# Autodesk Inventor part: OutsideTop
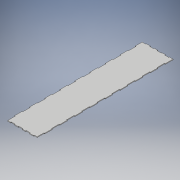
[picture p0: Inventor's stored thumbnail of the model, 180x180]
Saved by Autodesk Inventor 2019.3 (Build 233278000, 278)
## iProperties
Created: 2020-02
Part Number: OutsideTop
Material: Generic
Document SubType Name: Modeling
Designer: KrystynWikoff
Density: 1 g/cm^3
Appearance: Default
Author: KrystynWikoff
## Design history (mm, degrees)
sketch "Sketch1"
  geometry: L1 (0, 0)-(101.6, 0); L2 (101.6, 0)-(101.6, -457.2); L3 (101.6, -457.2)-(0, -457.2); L4 (0, -457.2)-(0, 0)
  constraints: 8 end point, 2 parallel, 1 horizontal, 1 perpendicular
  dimensions: "d0" = 457.2 distance of L3.end L1.start; "d1" = 101.6 distance of L1.start L1.end
extrude "Extrusion1" new body sketch "Sketch1" distance "d2" = 2.3622; taper "d3" = 0 deg
sketch "Sketch2" dims "d11" = 25.4
  geometry: L1 (-101.6, 0)-(0, 0) reference; L2 (0, 0)-(-2.362, 0); L3 (-2.362, 0)-(-2.362, 25.4); L4 (-2.362, 25.4)-(0, 25.4); L5 (0, 25.4)-(0, 0); L6 (0, 50.8)-(-2.362, 50.8); L7 (-2.362, 50.8)-(-2.362, 76.2); L8 (-2.362, 76.2)-(0, 76.2); L9 (0, 76.2)-(0, 50.8); L10 (0, 101.6)-(-2.362, 101.6); L11 (-2.362, 101.6)-(-2.362, 127); L12 (-2.362, 127)-(0, 127); L13 (0, 127)-(0, 101.6); L14 (0, 152.4)-(-2.362, 152.4); L15 (-2.362, 152.4)-(-2.362, 177.8); L16 (-2.362, 177.8)-(0, 177.8); L17 (0, 177.8)-(0, 152.4); L18 (0, 203.2)-(-2.362, 203.2); L19 (-2.362, 203.2)-(-2.362, 228.6); L20 (-2.362, 228.6)-(0, 228.6); L21 (0, 228.6)-(0, 203.2); L22 (0, 254)-(-2.362, 254); L23 (-2.362, 254)-(-2.362, 279.4); L24 (-2.362, 279.4)-(0, 279.4); L25 (0, 279.4)-(0, 254); L26 (0, 304.8)-(-2.362, 304.8); L27 (-2.362, 304.8)-(-2.362, 330.2); L28 (-2.362, 330.2)-(0, 330.2); L29 (0, 330.2)-(0, 304.8); L30 (0, 355.6)-(-2.362, 355.6); L31 (-2.362, 355.6)-(-2.362, 381); L32 (-2.362, 381)-(0, 381); L33 (0, 381)-(0, 355.6); L34 (0, 406.4)-(-2.362, 406.4); L35 (-2.362, 406.4)-(-2.362, 431.8); L36 (-2.362, 431.8)-(0, 431.8); L37 (0, 431.8)-(0, 406.4)
  constraints: 72 end point, 2 parallel, 1 collinear, 1 horizontal, 1 perpendicular, 1 vertical, 63 other
  dimensions: "d4" = 25.4 distance of L2.end L3.end; "d5" = 2.3622 distance of L3.end L4.end; "d8" = 50.8 distance of L3.end L7.end
extrude "Extrusion2" cut sketch "Sketch2" distance "d13" = 2.3622; taper "d14" = 0 deg
sketch "Sketch3" dims "d22" = 25.4, "d32" = 25.4
  geometry: L1 (0, 0)-(-12.7, 0); L2 (-12.7, 0)-(-12.7, 2.362); L3 (-12.7, 2.362)-(0, 2.362); L4 (0, 2.362)-(0, 0); L5 (-25.4, 0)-(-38.1, 0); L6 (-38.1, 0)-(-38.1, 2.362); L7 (-38.1, 2.362)-(-25.4, 2.362); L8 (-25.4, 2.362)-(-25.4, 0); L9 (-50.8, 0)-(-63.5, 0); L10 (-63.5, 0)-(-63.5, 2.362); L11 (-63.5, 2.362)-(-50.8, 2.362); L12 (-50.8, 2.362)-(-50.8, 0); L13 (-76.2, 0)-(-88.9, 0); L14 (-88.9, 0)-(-88.9, 2.362); L15 (-88.9, 2.362)-(-76.2, 2.362); L16 (-76.2, 2.362)-(-76.2, 0); L17 (-101.6, 0)-(-114.3, 0); L18 (-114.3, 0)-(-114.3, 2.362); L19 (-114.3, 2.362)-(-101.6, 2.362); L20 (-101.6, 2.362)-(-101.6, 0); L21 (0, 457.2)-(-101.6, 457.2) reference; L22 (-12.7, 457.2)-(-25.4, 457.2); L23 (-25.4, 457.2)-(-25.4, 454.838); L24 (-25.4, 454.838)-(-12.7, 454.838); L25 (-12.7, 454.838)-(-12.7, 457.2); L26 (0, 431.8)-(0, 457.2) reference; L27 (-50.8, 457.2)-(-50.8, 454.838); L28 (-50.8, 454.838)-(-38.1, 454.838); L29 (-38.1, 457.2)-(-50.8, 457.2); L30 (-38.1, 454.838)-(-38.1, 457.2); L31 (-76.2, 457.2)-(-76.2, 454.838); L32 (-76.2, 454.838)-(-63.5, 454.838); L33 (-63.5, 457.2)-(-76.2, 457.2); L34 (-63.5, 454.838)-(-63.5, 457.2); L35 (-101.6, 457.2)-(-101.6, 454.838); L36 (-101.6, 454.838)-(-88.9, 454.838); L37 (-88.9, 457.2)-(-101.6, 457.2); L38 (-88.9, 454.838)-(-88.9, 457.2)
  constraints: 72 end point, 4 horizontal, 4 parallel, 2 perpendicular, 1 collinear, 1 point on line, 55 other
  dimensions: "d15" = 12.7 distance of L2.end L3.end; "d16" = 2.3622 distance of L1.end L2.end; "d19" = 25.4 distance of L2.end L6.end; "d24" = 12.7 distance of L23.end L24.end; "d25" = 12.7 distance between parallel lines of L26 L25; "d26" = 2.3622 distance of L24.end L22.start; "d29" = 25.4 distance of L23.end L27.end
extrude "Extrusion3" cut sketch "Sketch3" distance "d34" = 2.3622; taper "d35" = 0 deg
sketch "Sketch4" dims "d44" = 25.4
  geometry: L1 (-101.6, 454.838)-(-101.6, 0) reference; L2 (-101.6, 25.4)-(-99.238, 25.4); L3 (-99.238, 25.4)-(-99.238, 0); L4 (-99.238, 0)-(-101.6, 0); L5 (-101.6, 0)-(-101.6, 25.4); L6 (-101.6, 0)-(-88.9, 0) reference; L7 (-101.6, 76.2)-(-99.238, 76.2); L8 (-99.238, 76.2)-(-99.238, 50.8); L9 (-99.238, 50.8)-(-101.6, 50.8); L10 (-101.6, 50.8)-(-101.6, 76.2); L11 (-101.6, 127)-(-99.238, 127); L12 (-99.238, 127)-(-99.238, 101.6); L13 (-99.238, 101.6)-(-101.6, 101.6); L14 (-101.6, 101.6)-(-101.6, 127); L15 (-101.6, 177.8)-(-99.238, 177.8); L16 (-99.238, 177.8)-(-99.238, 152.4); L17 (-99.238, 152.4)-(-101.6, 152.4); L18 (-101.6, 152.4)-(-101.6, 177.8); L19 (-101.6, 228.6)-(-99.238, 228.6); L20 (-99.238, 228.6)-(-99.238, 203.2); L21 (-99.238, 203.2)-(-101.6, 203.2); L22 (-101.6, 203.2)-(-101.6, 228.6); L23 (-101.6, 279.4)-(-99.238, 279.4); L24 (-99.238, 279.4)-(-99.238, 254); L25 (-99.238, 254)-(-101.6, 254); L26 (-101.6, 254)-(-101.6, 279.4); L27 (-101.6, 330.2)-(-99.238, 330.2); L28 (-99.238, 330.2)-(-99.238, 304.8); L29 (-99.238, 304.8)-(-101.6, 304.8); L30 (-101.6, 304.8)-(-101.6, 330.2); L31 (-101.6, 381)-(-99.238, 381); L32 (-99.238, 381)-(-99.238, 355.6); L33 (-99.238, 355.6)-(-101.6, 355.6); L34 (-101.6, 355.6)-(-101.6, 381); L35 (-101.6, 431.8)-(-99.238, 431.8); L36 (-99.238, 431.8)-(-99.238, 406.4); L37 (-99.238, 406.4)-(-101.6, 406.4); L38 (-101.6, 406.4)-(-101.6, 431.8); 1 further point
  constraints: 72 end point, 2 parallel, 1 horizontal, 1 perpendicular, 1 point on line, 1 vertical, 64 other
  dimensions: "d36" = 25.4 distance of L2.end L3.end; "d37" = 2.3622 distance of L2.start L2.end; "d38" = 25.4 distance between parallel lines of L6 L2; "d41" = 50.8 distance of L2.start L7.start
extrude "Extrusion4" cut sketch "Sketch4" distance "d46" = 25.4; taper "d47" = 0 deg
body "Solid1"
